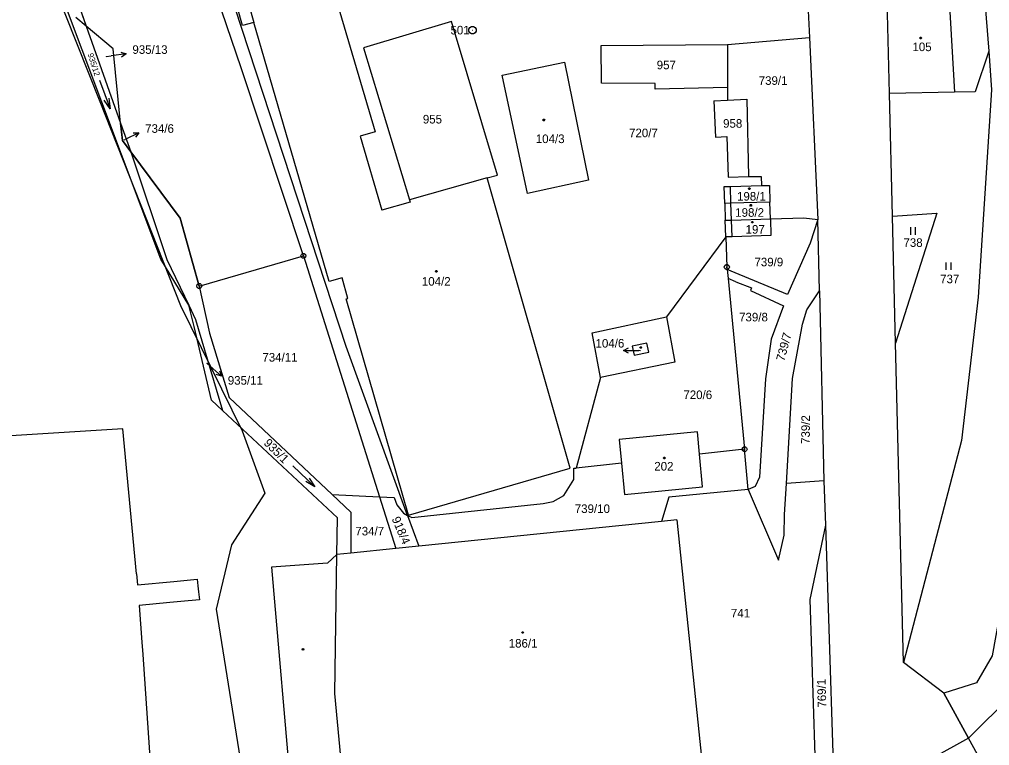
# Model space of a CAD drawing. Extents: x -580551 to -575069, y -1073031 to -1067931.
# Drawn here: x -578576.7 to -578384.9, y -1071266.5 to -1071122.8 of the extents above; entities that cross this region are included whole.
import ezdxf

# ---------------------------------------------------------------- set-up
doc = ezdxf.new("R2010")
doc.units = 0
for name, color, linetype in [('Druh pozemku', 7, 'Continuous'), ('Geodetické body', 7, 'Continuous'), ('Hranice státní', 7, 'Continuous'), ('Hranice z rastru', 7, 'Continuous'), ('Katastrální hranice', 7, 'Continuous'), ('Parcela', 7, 'Continuous'), ('Parcelní číslo', 7, 'Continuous'), ('Parcelní číslo_stavba', 7, 'Continuous'), ('Pomocná vrstva', 7, 'Continuous'), ('SR - hranice státu', 7, 'Continuous'), ('Vnitřní kresba', 7, 'Continuous')]:
    doc.layers.add(name, color=color, linetype=linetype)

msp = doc.modelspace()

# ---------------------------------------------------------------- linework, layer by layer
at = {"layer": 'Druh pozemku'}
for p, q in [((-578560.832, -1071134.887), (-578558.748, -1071140.513)), ((-578400.51, -1071163.94), (-578400.51, -1071165.44)), ((-578399.51, -1071165.44), (-578399.51, -1071163.94)), ((-578393.48, -1071170.92), (-578393.48, -1071172.42)), ((-578392.48, -1071172.42), (-578392.48, -1071170.92)), ((-578522.636, -1071211.195), (-578518.284, -1071215.325))]:
    msp.add_line(p, q, dxfattribs=at)
for points in [[(-578398.41, -1071126.38), (-578398.32, -1071126.53), (-578398.41, -1071126.68), (-578398.59, -1071126.68), (-578398.68, -1071126.53), (-578398.59, -1071126.38)], [(-578472.92, -1071142.61), (-578472.83, -1071142.76), (-578472.92, -1071142.91), (-578473.1, -1071142.91), (-578473.19, -1071142.76), (-578473.1, -1071142.61)], [(-578432.28, -1071156.2), (-578432.19, -1071156.35), (-578432.28, -1071156.5), (-578432.46, -1071156.5), (-578432.55, -1071156.35), (-578432.46, -1071156.2)], [(-578431.98, -1071159.48), (-578431.89, -1071159.63), (-578431.98, -1071159.78), (-578432.16, -1071159.78), (-578432.25, -1071159.63), (-578432.16, -1071159.48)], [(-578431.68, -1071162.81), (-578431.59, -1071162.96), (-578431.68, -1071163.11), (-578431.86, -1071163.11), (-578431.95, -1071162.96), (-578431.86, -1071162.81)], [(-578494.15, -1071172.53), (-578494.06, -1071172.68), (-578494.15, -1071172.83), (-578494.33, -1071172.83), (-578494.42, -1071172.68), (-578494.33, -1071172.53)], [(-578453.74, -1071187.62), (-578453.65, -1071187.77), (-578453.74, -1071187.92), (-578453.92, -1071187.92), (-578454.01, -1071187.77), (-578453.92, -1071187.62)], [(-578449.07, -1071209.48), (-578448.98, -1071209.63), (-578449.07, -1071209.78), (-578449.25, -1071209.78), (-578449.34, -1071209.63), (-578449.25, -1071209.48)], [(-578477.08, -1071244), (-578476.99, -1071244.15), (-578477.08, -1071244.3), (-578477.26, -1071244.3), (-578477.35, -1071244.15), (-578477.26, -1071244)], [(-578520.54, -1071247.34), (-578520.45, -1071247.49), (-578520.54, -1071247.64), (-578520.72, -1071247.64), (-578520.81, -1071247.49), (-578520.72, -1071247.34)]]:
    msp.add_lwpolyline(points, close=True, dxfattribs=at)
for points in [[(-578558.974, -1071138.464), (-578558.748, -1071140.513), (-578559.912, -1071138.811)], [(-578519.39, -1071213.586), (-578518.284, -1071215.325), (-578520.079, -1071214.311)]]:
    msp.add_lwpolyline(points, dxfattribs=at)
at = {"layer": 'Geodetické body'}
for p, q in [((-578487.13, -1071124.97), (-578487.03, -1071124.97)), ((-578520.64, -1071169.64), (-578520.4, -1071169.64)), ((-578436.93, -1071171.85), (-578436.69, -1071171.85)), ((-578541.24, -1071175.61), (-578541, -1071175.61)), ((-578433.42, -1071207.89), (-578433.18, -1071207.89))]:
    msp.add_line(p, q, dxfattribs=at)
for points in [[(-578486.89, -1071124.25), (-578486.55, -1071124.44), (-578486.36, -1071124.78), (-578486.36, -1071125.17), (-578486.55, -1071125.51), (-578486.89, -1071125.7), (-578487.28, -1071125.7), (-578487.62, -1071125.51), (-578487.81, -1071125.17), (-578487.81, -1071124.78), (-578487.62, -1071124.44), (-578487.28, -1071124.25)], [(-578520.37, -1071169.16), (-578520.12, -1071169.34), (-578520.02, -1071169.63), (-578520.12, -1071169.92), (-578520.37, -1071170.1), (-578520.68, -1071170.1), (-578520.93, -1071169.92), (-578521.03, -1071169.63), (-578520.93, -1071169.34), (-578520.68, -1071169.16)], [(-578436.66, -1071171.37), (-578436.41, -1071171.55), (-578436.31, -1071171.84), (-578436.41, -1071172.13), (-578436.66, -1071172.31), (-578436.97, -1071172.31), (-578437.22, -1071172.13), (-578437.32, -1071171.84), (-578437.22, -1071171.55), (-578436.97, -1071171.37)], [(-578540.97, -1071175.13), (-578540.72, -1071175.31), (-578540.62, -1071175.6), (-578540.72, -1071175.89), (-578540.97, -1071176.07), (-578541.28, -1071176.07), (-578541.53, -1071175.89), (-578541.63, -1071175.6), (-578541.53, -1071175.31), (-578541.28, -1071175.13)], [(-578433.15, -1071207.41), (-578432.9, -1071207.59), (-578432.8, -1071207.88), (-578432.9, -1071208.17), (-578433.15, -1071208.35), (-578433.46, -1071208.35), (-578433.71, -1071208.17), (-578433.81, -1071207.88), (-578433.71, -1071207.59), (-578433.46, -1071207.41)]]:
    msp.add_lwpolyline(points, close=True, dxfattribs=at)
at = {"layer": 'Hranice státní'}
for points in [[(-578553.56, -1071232.54), (-578556.24, -1071203.85), (-578632.3, -1071208.58), (-578631.87, -1071215.97)], [(-578553.56, -1071232.54), (-578553.36, -1071234.72), (-578546.15, -1071234.05), (-578541.54, -1071233.62), (-578541.4, -1071234.94), (-578541.27, -1071236.11), (-578541.1, -1071237.68), (-578544.79, -1071238.02), (-578546.95, -1071238.22), (-578552.98, -1071238.78), (-578552.47, -1071246.09)], [(-578552.47, -1071246.09), (-578552.3, -1071248.53), (-578550.21, -1071278.52), (-578548.05, -1071309.81), (-578573.99, -1071311.43)]]:
    msp.add_lwpolyline(points, dxfattribs=at)
at = {"layer": 'Hranice z rastru'}
msp.add_lwpolyline([(-578566.72, -1070947.779), (-578583.48, -1070998.532), (-578590.876, -1071020.93), (-578592.521, -1071043.374), (-578590.032, -1071060.419), (-578576.797, -1071098.705), (-578560.811, -1071139.089), (-578544.825, -1071179.473), (-578532.639, -1071204.254), (-578528.184, -1071216.579), (-578534.736, -1071226.806), (-578537.749, -1071239.524), (-578532.246, -1071274.139), (-578521.632, -1071309.672), (-578516.391, -1071321.603), (-578520.977, -1071339.96), (-578529.232, -1071361.069)], dxfattribs=at)
at = {"layer": 'Katastrální hranice'}
for p, q in [((-578548.7, -1071170.29), (-578571.03, -1071110.79)), ((-578543.21, -1071179.41), (-578548.7, -1071170.29)), ((-578542.12, -1071183.61), (-578543.21, -1071179.41)), ((-578538.68, -1071198.16), (-578542.12, -1071183.61)), ((-578536.5, -1071200.21), (-578538.68, -1071198.16)), ((-578513.82, -1071221.47), (-578536.5, -1071200.21)), ((-578513.93, -1071228.71), (-578513.82, -1071221.47)), ((-578514.34, -1071256.25), (-578513.93, -1071228.71)), ((-578512.42, -1071276.06), (-578514.34, -1071256.25))]:
    msp.add_line(p, q, dxfattribs=at)
at = {"layer": 'Parcela'}
for p, q in [((-578568.52, -1071109.92), (-578563.47, -1071124.19)), ((-578386.49, -1071109.82), (-578385.04, -1071129.14)), ((-578515.21, -1071114.91), (-578506.34, -1071145.08)), ((-578420.92, -1071117.09), (-578420.49, -1071126.46)), ((-578404.66, -1071137.52), (-578405.11, -1071119.06)), ((-578532.82, -1071132.45), (-578536.67, -1071121.21)), ((-578512.07, -1071187.59), (-578534.03, -1071120.61)), ((-578532.55, -1071124.08), (-578533.56, -1071120.59)), ((-578563.47, -1071124.19), (-578565.51, -1071122.46)), ((-578530.33, -1071123.43), (-578532.55, -1071124.08)), ((-578515.42, -1071174.69), (-578530.33, -1071123.43)), ((-578491.25, -1071123.23), (-578508.62, -1071128.49)), ((-578482.17, -1071153.65), (-578491.25, -1071123.23)), ((-578558.15, -1071128.7), (-578563.47, -1071124.19)), ((-578563.47, -1071124.19), (-578556.68, -1071143.37)), ((-578436.67, -1071127.84), (-578420.49, -1071126.46)), ((-578420.49, -1071126.46), (-578418.82, -1071162.47)), ((-578556.68, -1071143.37), (-578558.15, -1071128.7)), ((-578508.62, -1071128.49), (-578499.56, -1071158.55)), ((-578461.64, -1071127.99), (-578436.67, -1071127.84)), ((-578461.61, -1071135.48), (-578461.64, -1071127.99)), ((-578436.67, -1071127.84), (-578436.67, -1071136.35)), ((-578385.04, -1071129.14), (-578387.71, -1071137.19)), ((-578385.04, -1071129.14), (-578384.46, -1071136.79)), ((-578481.22, -1071133.86), (-578468.9, -1071131.31)), ((-578468.9, -1071131.31), (-578464.16, -1071154.68)), ((-578520.52, -1071169.64), (-578532.82, -1071132.45)), ((-578476.2, -1071157.32), (-578481.22, -1071133.86)), ((-578450.99, -1071135.5), (-578461.61, -1071135.48)), ((-578450.99, -1071136.63), (-578450.99, -1071135.5)), ((-578436.67, -1071136.35), (-578450.99, -1071136.63)), ((-578436.67, -1071136.35), (-578436.67, -1071138.81)), ((-578391.78, -1071137.27), (-578404.66, -1071137.52)), ((-578387.71, -1071137.19), (-578391.78, -1071137.27)), ((-578384.46, -1071136.79), (-578387.12, -1071177.78)), ((-578439.38, -1071138.93), (-578436.67, -1071138.81)), ((-578439.38, -1071138.93), (-578439.05, -1071146.12)), ((-578436.67, -1071138.81), (-578432.83, -1071138.63)), ((-578432.83, -1071138.63), (-578432.55, -1071153.96)), ((-578404.06, -1071161.77), (-578404.66, -1071137.52)), ((-578556.68, -1071143.37), (-578554.67, -1071149.03)), ((-578556.33, -1071146.81), (-578556.68, -1071143.37)), ((-578554.67, -1071149.03), (-578556.33, -1071146.81)), ((-578506.34, -1071145.08), (-578509.31, -1071145.95)), ((-578509.31, -1071145.95), (-578505, -1071160.6)), ((-578439.05, -1071146.12), (-578436.8, -1071146.04)), ((-578436.8, -1071146.04), (-578436.52, -1071154.05)), ((-578554.67, -1071149.03), (-578547.55, -1071170.33)), ((-578544.89, -1071162.17), (-578554.67, -1071149.03)), ((-578484.17, -1071154.21), (-578499.56, -1071158.55)), ((-578484.17, -1071154.21), (-578482.17, -1071153.65)), ((-578467.76, -1071211.67), (-578484.17, -1071154.21)), ((-578436.52, -1071154.05), (-578432.55, -1071153.96)), ((-578432.55, -1071153.96), (-578430.03, -1071153.91)), ((-578430.03, -1071153.91), (-578429.99, -1071155.74)), ((-578464.16, -1071154.68), (-578476.2, -1071157.32)), ((-578437.31, -1071155.94), (-578436.11, -1071155.91)), ((-578437.21, -1071159.27), (-578437.31, -1071155.94)), ((-578436.11, -1071155.91), (-578429.99, -1071155.74)), ((-578429.99, -1071155.74), (-578428.41, -1071155.69)), ((-578428.41, -1071155.69), (-578428.31, -1071158.99)), ((-578499.42, -1071159.03), (-578505, -1071160.6)), ((-578499.56, -1071158.55), (-578499.42, -1071159.03)), ((-578436, -1071159.24), (-578437.21, -1071159.27)), ((-578437.21, -1071159.27), (-578437.11, -1071162.6)), ((-578428.31, -1071158.99), (-578436, -1071159.24)), ((-578428.21, -1071162.29), (-578428.31, -1071158.99)), ((-578541.12, -1071175.61), (-578544.89, -1071162.17)), ((-578435.89, -1071162.56), (-578428.21, -1071162.29)), ((-578428.21, -1071162.29), (-578421.59, -1071162.08)), ((-578428.21, -1071162.29), (-578428.11, -1071165.59)), ((-578421.59, -1071162.08), (-578418.82, -1071162.47)), ((-578404.06, -1071161.77), (-578395.27, -1071161.16)), ((-578403.45, -1071186.92), (-578404.06, -1071161.77)), ((-578395.27, -1071161.16), (-578403.45, -1071186.92)), ((-578437.11, -1071162.6), (-578435.89, -1071162.56)), ((-578437.01, -1071165.9), (-578437.11, -1071162.6)), ((-578418.82, -1071162.47), (-578420.31, -1071167.14)), ((-578418.47, -1071176.58), (-578418.82, -1071162.47)), ((-578437.01, -1071165.9), (-578448.73, -1071181.71)), ((-578435.78, -1071165.86), (-578437.01, -1071165.9)), ((-578437.01, -1071165.9), (-578436.81, -1071171.85)), ((-578428.11, -1071165.59), (-578435.78, -1071165.86)), ((-578420.31, -1071167.14), (-578424.83, -1071177.31)), ((-578541.12, -1071175.61), (-578520.52, -1071169.64)), ((-578520.52, -1071169.64), (-578505.49, -1071217.29)), ((-578547.55, -1071170.33), (-578543.21, -1071179.41)), ((-578436.81, -1071171.85), (-578436.76, -1071172.33)), ((-578435.19, -1071172.99), (-578436.76, -1071172.33)), ((-578436.76, -1071172.33), (-578436.58, -1071174.13)), ((-578424.83, -1071177.31), (-578435.19, -1071172.99)), ((-578541.12, -1071175.61), (-578539.07, -1071184.94)), ((-578512.9, -1071173.97), (-578515.42, -1071174.69)), ((-578511.72, -1071178.06), (-578512.9, -1071173.97)), ((-578435.04, -1071174.74), (-578436.58, -1071174.13)), ((-578436.58, -1071174.13), (-578433.3, -1071207.89)), ((-578435.04, -1071174.74), (-578431.91, -1071175.99)), ((-578431.91, -1071175.99), (-578432.11, -1071176.48)), ((-578432.11, -1071176.48), (-578425.59, -1071179.53)), ((-578421.02, -1071180.28), (-578418.47, -1071176.58)), ((-578418.47, -1071176.58), (-578417.63, -1071214.12)), ((-578543.21, -1071179.41), (-578541.87, -1071182.2)), ((-578512.06, -1071178.16), (-578511.72, -1071178.06)), ((-578499.73, -1071220.92), (-578512.06, -1071178.16)), ((-578425.59, -1071179.53), (-578428.03, -1071186.09)), ((-578387.12, -1071177.78), (-578390.4, -1071206.16)), ((-578421.85, -1071183.16), (-578421.02, -1071180.28)), ((-578541.87, -1071182.2), (-578536.5, -1071200.21)), ((-578463.44, -1071184.88), (-578448.73, -1071181.71)), ((-578448.73, -1071181.71), (-578447.07, -1071190.65)), ((-578423.85, -1071193.92), (-578421.85, -1071183.16)), ((-578539.07, -1071184.94), (-578535.22, -1071197.63)), ((-578461.8, -1071193.73), (-578463.44, -1071184.88)), ((-578428.03, -1071186.09), (-578429.14, -1071193.96)), ((-578401.91, -1071250.1), (-578403.45, -1071186.92)), ((-578499.94, -1071220.98), (-578512.07, -1071187.59)), ((-578447.07, -1071190.65), (-578461.8, -1071193.73)), ((-578461.8, -1071193.73), (-578466.61, -1071211.64)), ((-578429.14, -1071193.96), (-578430.35, -1071213.39)), ((-578425.03, -1071214.67), (-578423.85, -1071193.92)), ((-578535.22, -1071197.63), (-578514.86, -1071216.88)), ((-578442.64, -1071204.42), (-578458.12, -1071205.94)), ((-578442.23, -1071208.89), (-578442.64, -1071204.42)), ((-578458.12, -1071205.94), (-578457.66, -1071210.63)), ((-578390.4, -1071206.16), (-578401.91, -1071250.1)), ((-578433.3, -1071207.89), (-578442.23, -1071208.89)), ((-578432.61, -1071215.89), (-578433.3, -1071207.89)), ((-578441.63, -1071215.34), (-578442.23, -1071208.89)), ((-578499.73, -1071220.92), (-578467.76, -1071211.67)), ((-578467.07, -1071213.9), (-578467.08, -1071211.64)), ((-578467.08, -1071211.64), (-578466.61, -1071211.64)), ((-578457.66, -1071210.63), (-578466.61, -1071211.64)), ((-578457.66, -1071210.63), (-578457.05, -1071216.85)), ((-578469.04, -1071217.03), (-578467.07, -1071213.9)), ((-578430.35, -1071213.39), (-578431.22, -1071215.24)), ((-578457.05, -1071216.85), (-578441.63, -1071215.34)), ((-578432.61, -1071215.89), (-578448.29, -1071217.36)), ((-578431.22, -1071215.24), (-578432.61, -1071215.89)), ((-578432.61, -1071215.89), (-578426.62, -1071229.85)), ((-578425.38, -1071220.8), (-578425.03, -1071214.67)), ((-578417.63, -1071214.12), (-578425.03, -1071214.67)), ((-578417.63, -1071214.12), (-578417.28, -1071222.89)), ((-578514.86, -1071216.88), (-578511.18, -1071220.36)), ((-578514.86, -1071216.88), (-578505.49, -1071217.29)), ((-578505.49, -1071217.29), (-578502.61, -1071217.42)), ((-578505.49, -1071217.29), (-578502.26, -1071227.52)), ((-578502.61, -1071217.42), (-578502.03, -1071218.87)), ((-578471.17, -1071218.21), (-578469.04, -1071217.03)), ((-578448.29, -1071217.36), (-578449.74, -1071222.18)), ((-578502.03, -1071218.87), (-578500.77, -1071220.56)), ((-578499.07, -1071221.43), (-578473.1, -1071218.64)), ((-578473.1, -1071218.64), (-578471.17, -1071218.21)), ((-578511.18, -1071220.36), (-578511.17, -1071228.43)), ((-578500.77, -1071220.56), (-578499.94, -1071220.98)), ((-578499.73, -1071220.92), (-578499.94, -1071220.98)), ((-578499.94, -1071220.98), (-578499.07, -1071221.43)), ((-578499.94, -1071220.98), (-578497.72, -1071227.06)), ((-578425.47, -1071224.9), (-578425.38, -1071220.8)), ((-578449.74, -1071222.18), (-578497.72, -1071227.06)), ((-578446.68, -1071221.87), (-578449.74, -1071222.18)), ((-578446.68, -1071221.87), (-578441.84, -1071268.91)), ((-578417.28, -1071222.89), (-578420.39, -1071237.61)), ((-578417.28, -1071222.89), (-578415.83, -1071268.01)), ((-578426.62, -1071229.85), (-578425.47, -1071224.9)), ((-578502.26, -1071227.52), (-578511.17, -1071228.43)), ((-578497.72, -1071227.06), (-578502.26, -1071227.52)), ((-578511.17, -1071228.43), (-578513.93, -1071228.71)), ((-578420.39, -1071237.61), (-578419.43, -1071268.52)), ((-578393.93, -1071256.14), (-578401.91, -1071250.1)), ((-578384.32, -1071248.78), (-578387.44, -1071254.1)), ((-578387.44, -1071254.1), (-578393.93, -1071256.14)), ((-578389.04, -1071265.06), (-578393.93, -1071256.14)), ((-578379.75, -1071255.8), (-578389.04, -1071265.06)), ((-578385.4, -1071271.68), (-578389.04, -1071265.06))]:
    msp.add_line(p, q, dxfattribs=at)
at = {"layer": 'Pomocná vrstva'}
for p, q in [((-578555.576, -1071129.673), (-578558.55, -1071130.07)), ((-578559.56, -1071130.2), (-578558.55, -1071130.07)), ((-578555.96, -1071146.67), (-578555.77, -1071146.58)), ((-578553.062, -1071145.29), (-578555.77, -1071146.58)), ((-578457.24, -1071188.337), (-578454.24, -1071188.39)), ((-578453.86, -1071188.4), (-578454.24, -1071188.39)), ((-578539.62, -1071190.87), (-578538.97, -1071191.44)), ((-578536.717, -1071193.421), (-578538.97, -1071191.44))]:
    msp.add_line(p, q, dxfattribs=at)
for points in [[(-578556.634, -1071129.31), (-578555.576, -1071129.673), (-578556.501, -1071130.301)], [(-578554.179, -1071145.268), (-578553.062, -1071145.29), (-578553.749, -1071146.171)], [(-578456.249, -1071188.854), (-578457.24, -1071188.337), (-578456.231, -1071187.854)], [(-578537.138, -1071192.385), (-578536.717, -1071193.421), (-578537.798, -1071193.136)]]:
    msp.add_lwpolyline(points, dxfattribs=at)
at = {"layer": 'SR - hranice státu'}
for points in [[(-578586.18, -1071013.95), (-578588.3, -1071042.01), (-578586.77, -1071057.49), (-578582.9, -1071071.43), (-578580.97, -1071076.59), (-578576.15, -1071089.49), (-578568.52, -1071109.92), (-578563.47, -1071124.19), (-578556.68, -1071143.37)], [(-578556.68, -1071143.37), (-578556.33, -1071146.81), (-578554.67, -1071149.03)], [(-578554.67, -1071149.03), (-578544.89, -1071162.17), (-578541.12, -1071175.61), (-578539.07, -1071184.94), (-578535.22, -1071197.63), (-578514.86, -1071216.88), (-578511.18, -1071220.36), (-578511.17, -1071228.43), (-578513.93, -1071228.71)], [(-578367.78, -1071172.91), (-578372.57, -1071207.64), (-578382.77, -1071239.97), (-578384.32, -1071248.78), (-578387.44, -1071254.1), (-578393.93, -1071256.14), (-578389.04, -1071265.06)], [(-578513.93, -1071228.71), (-578515.74, -1071230.46), (-578526.81, -1071231.26), (-578522.85, -1071277.67), (-578517.09, -1071277.68)], [(-578389.04, -1071265.06), (-578404.15, -1071273.47), (-578415.83, -1071268.01), (-578426.53, -1071289.74)]]:
    msp.add_lwpolyline(points, dxfattribs=at)
at = {"layer": 'Vnitřní kresba'}
for p, q in [((-578531.32, -1071119.94), (-578530.33, -1071123.43)), ((-578392.88, -1071119.01), (-578391.78, -1071137.27)), ((-578436, -1071159.24), (-578436.11, -1071155.91)), ((-578435.89, -1071162.56), (-578436, -1071159.24)), ((-578435.78, -1071165.86), (-578435.89, -1071162.56)), ((-578452.62, -1071186.88), (-578455.5, -1071187.51)), ((-578452.23, -1071188.66), (-578452.62, -1071186.88)), ((-578455.5, -1071187.51), (-578455.11, -1071189.29)), ((-578455.11, -1071189.29), (-578452.23, -1071188.66))]:
    msp.add_line(p, q, dxfattribs=at)

# ---------------------------------------------------------------- texts
at = {"layer": 'Geodetické body'}
msp.add_text('501', height=1.7, dxfattribs=at).set_placement((-578491.451, -1071125.82))
at = {"layer": 'Parcelní číslo'}
for s, height, rotation, p in [('935/12', 1.14, 287.62481, (-578563.199, -1071129.738)), ('739/7', 1.7, 75.11477, (-578425.46, -1071190.593)), ('739/2', 1.7, 89.38142, (-578420.424, -1071206.855)), ('935/1', 1.7, 315.41327, (-578528.493, -1071206.826)), ('918/4', 1.7, 292.89603, (-578503.108, -1071221.651)), ('769/1', 1.7, 91.61595, (-578417.134, -1071258.996))]:
    msp.add_text(s, height=height, rotation=rotation, dxfattribs=at).set_placement(p)
for s, height, p in [('935/13', 0.1, (-578559.795, -1071130.2)), ('957', 1.7, (-578450.68, -1071132.71)), ('739/1', 1.7, (-578430.514, -1071135.8)), ('955', 1.7, (-578496.917, -1071143.44)), ('958', 1.7, (-578437.553, -1071144.28)), ('720/7', 1.7, (-578456.147, -1071146.16)), ('734/6', 0.1, (-578556.165, -1071146.67)), ('738', 1.7, (-578401.893, -1071167.86)), ('739/9', 1.7, (-578431.351, -1071171.7)), ('737', 1.7, (-578394.64, -1071175.05)), ('739/8', 1.7, (-578434.388, -1071182.6)), ('734/11', 1.7, (-578528.645, -1071190.55)), ('935/11', 0.1, (-578539.829, -1071190.87)), ('720/6', 1.7, (-578445.402, -1071197.97)), ('739/10', 1.7, (-578466.875, -1071220.51)), ('734/7', 1.7, (-578510.265, -1071224.95)), ('741', 1.7, (-578436.012, -1071241.18))]:
    msp.add_text(s, height=height, dxfattribs=at).set_placement(p)
at = {"layer": 'Parcelní číslo_stavba'}
for s, height, p in [('105', 1.7, (-578400.112, -1071129.13)), ('104/3', 1.7, (-578474.583, -1071147.32)), ('198/1', 1.7, (-578434.799, -1071158.7)), ('198/2', 1.7, (-578435.151, -1071161.9)), ('197', 1.7, (-578433.102, -1071165.24)), ('104/2', 1.7, (-578497.111, -1071175.53)), ('104/6', 0.1, (-578454.043, -1071188.4)), ('202', 1.7, (-578451.158, -1071212.11)), ('186/1', 1.7, (-578479.939, -1071247.14))]:
    msp.add_text(s, height=height, dxfattribs=at).set_placement(p)
at = {"layer": 'Pomocná vrstva'}
for s, p in [('935/13', (-578554.343, -1071129.67)), ('734/6', (-578551.823, -1071145.29)), ('104/6', (-578462.77, -1071187.78)), ('935/11', (-578535.483, -1071195.12))]:
    msp.add_text(s, height=1.7, dxfattribs=at).set_placement(p)

doc.saveas('drawing.dxf')
